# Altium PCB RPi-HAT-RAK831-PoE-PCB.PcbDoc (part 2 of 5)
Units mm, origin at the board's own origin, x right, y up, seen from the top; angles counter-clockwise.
Board outline 65 x 56 mm, 2 copper layers (Top Layer, Bottom Layer); 9 components, 14 nets, 9110 pads, 249 vias.
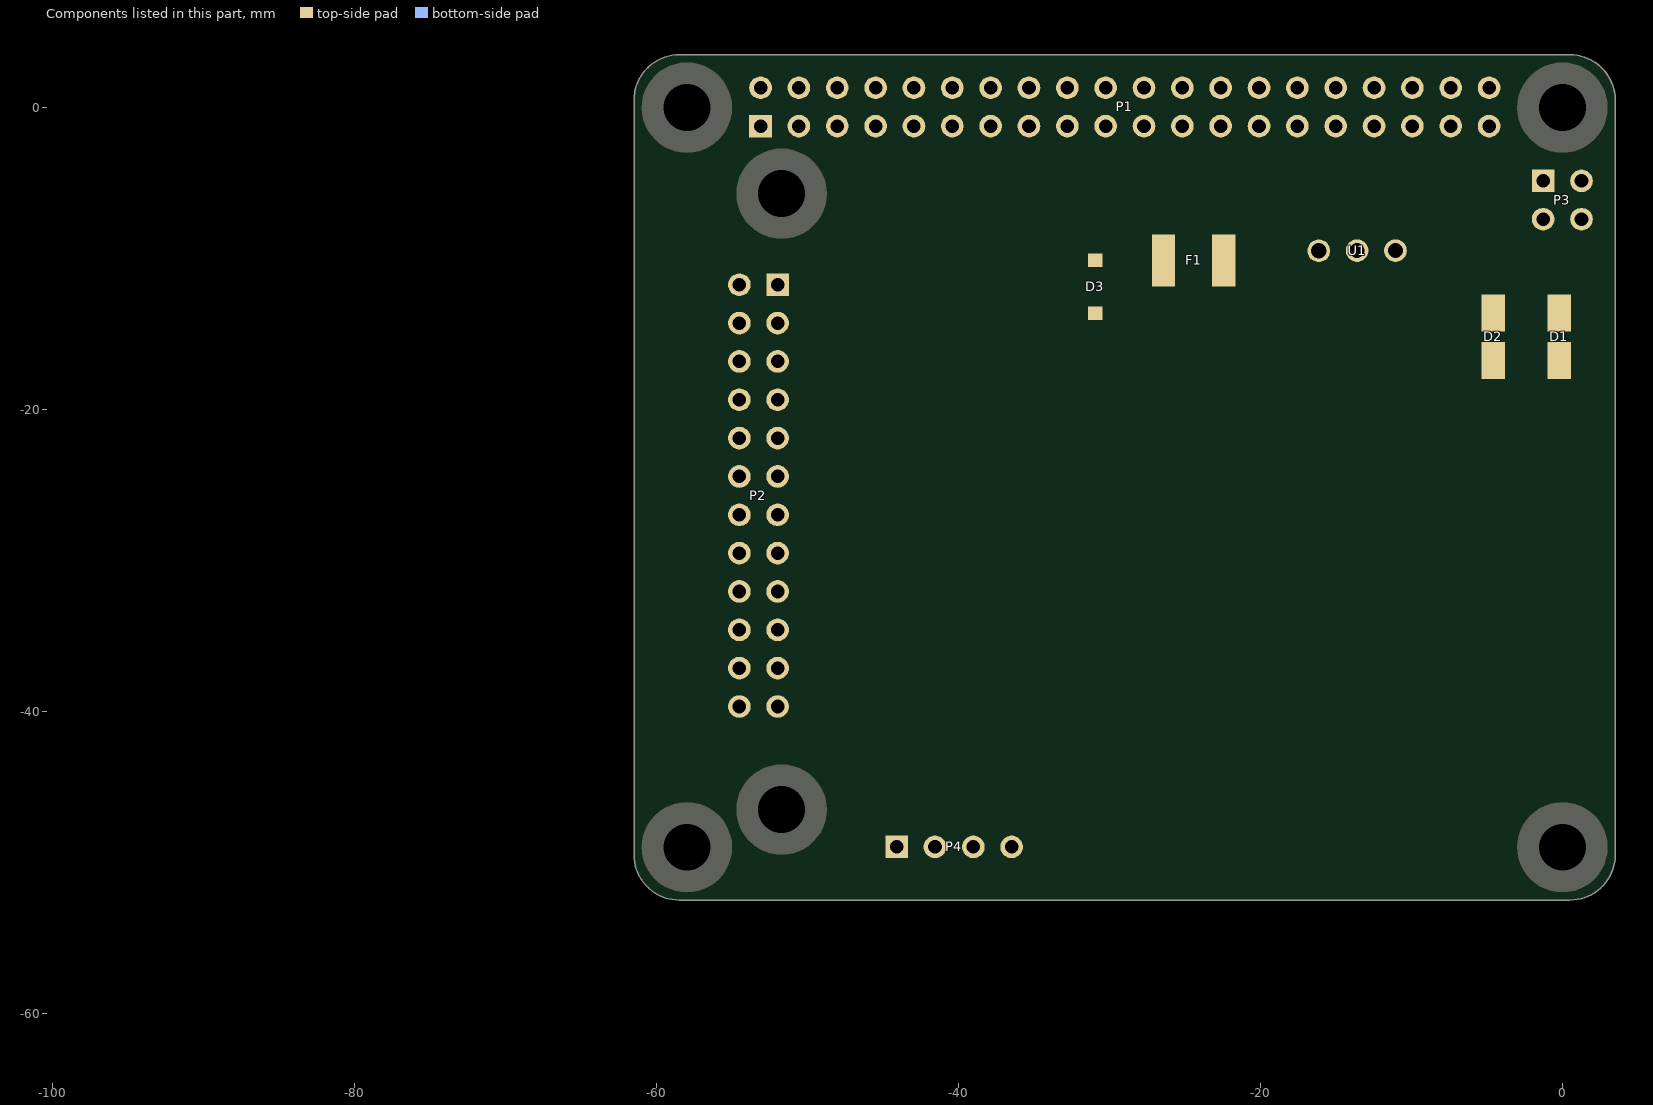
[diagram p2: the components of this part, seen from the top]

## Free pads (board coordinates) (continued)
  round 0.025 on Bottom Overlay: 1(-36.025,-43.237) 1(-36.025,-43.212) 1(-36.025,-43.186) 1(-36,-43.288) 1(-36,-43.263) 1(-35.975,-43.364) 1(-35.975,-43.339) 1(-35.975,-43.313) 1(-35.949,-43.415) 1(-35.949,-43.39) 1(-35.924,-43.491) 1(-35.924,-43.466) 1(-35.924,-43.44) 1(-35.898,-43.567) 1(-35.898,-43.542) 1(-35.898,-43.517) 1(-35.873,-43.618) 1(-35.873,-43.593) 1(-35.848,-43.694) 1(-35.848,-43.669) 1(-35.848,-43.644) 1(-35.822,-43.745) 1(-35.822,-43.72) 1(-35.797,-43.821) 1(-35.797,-43.796) 1(-35.797,-43.771) 1(-35.771,-43.898) 1(-35.771,-43.872) 1(-35.771,-43.847) 1(-35.746,-43.948) 1(-35.746,-43.923) 1(-35.721,-44.025) 1(-35.721,-43.999) 1(-35.721,-43.974) 1(-35.695,-44.101) 1(-35.695,-44.075) 1(-35.695,-44.05) 1(-35.67,-44.152) 1(-35.67,-44.126) 1(-35.644,-44.228) 1(-35.644,-44.202) 1(-35.644,-44.177) 1(-35.619,-44.279) 1(-35.619,-44.253) 1(-35.594,-44.355) 1(-35.594,-44.329) 1(-35.594,-44.304) 1(-35.568,-44.431) 1(-35.568,-44.406) 1(-35.568,-44.38) 1(-35.543,-44.482) 1(-35.543,-44.456) 1(-35.517,-44.558) 1(-35.517,-44.533) 1(-35.517,-44.507) 1(-35.492,-44.609) 1(-35.492,-44.583) 1(-35.467,-44.685) 1(-35.467,-44.66) 1(-35.467,-44.634) 1(-35.441,-44.761) 1(-35.441,-44.736) 1(-35.441,-44.71) 1(-35.416,-44.812) 1(-35.416,-44.787) 1(-35.39,-44.888) 1(-35.39,-44.863) 1(-35.39,-44.837) 1(-35.365,-44.939) 1(-35.365,-44.914) 1(-35.34,-45.015) 1(-35.34,-44.99) 1(-35.34,-44.964) 1(-35.314,-45.091) 1(-35.314,-45.066) 1(-35.314,-45.041) 1(-35.289,-45.142) 1(-35.289,-45.117) 1(-35.263,-45.218) 1(-35.263,-45.193) 1(-35.263,-45.168) 1(-35.238,-45.269) 1(-35.238,-45.244) 1(-35.213,-45.345) 1(-35.213,-45.32) 1(-35.213,-45.295) 1(-35.213,-43.186) 1(-35.187,-45.422) 1(-35.187,-45.396) 1(-35.187,-45.371) 1(-35.187,-43.263) 1(-35.187,-43.237) 1(-35.187,-43.212) 1(-35.162,-45.472) 1(-35.162,-45.447) 1(-35.162,-43.339) 1(-35.162,-43.313) 1(-35.162,-43.288) 1(-35.136,-45.549) 1(-35.136,-45.523) 1(-35.136,-45.498) 1(-35.136,-43.415) 1(-35.136,-43.39) 1(-35.136,-43.364) 1(-35.111,-45.599) 1(-35.111,-45.574) 1(-35.111,-43.491) 1(-35.111,-43.466) 1(-35.111,-43.44) 1(-35.086,-45.676) 1(-35.086,-45.65) 1(-35.086,-45.625) 1(-35.086,-43.567) 1(-35.086,-43.542) 1(-35.086,-43.517) 1(-35.06,-45.752) 1(-35.06,-45.726) 1(-35.06,-45.701) 1(-35.06,-43.644) 1(-35.06,-43.618) 1(-35.06,-43.593) 1(-35.035,-45.803) 1(-35.035,-45.777) 1(-35.035,-43.72) 1(-35.035,-43.694) 1(-35.035,-43.669) 1(-35.009,-45.879) 1(-35.009,-45.853) 1(-35.009,-45.828) 1(-35.009,-43.796) 1(-35.009,-43.771) 1(-35.009,-43.745) 1(-34.984,-45.955) 1(-34.984,-45.93) 1(-34.984,-45.904) 1(-34.984,-43.898) 1(-34.984,-43.872) 1(-34.984,-43.847) 1(-34.984,-43.821) 1(-34.959,-46.006) 1(-34.959,-45.98) 1(-34.959,-43.974) 1(-34.959,-43.948) 1(-34.959,-43.923) 1(-34.933,-46.082) 1(-34.933,-46.057) 1(-34.933,-46.031) 1(-34.933,-44.05) 1(-34.933,-44.025) 1(-34.933,-43.999) 1(-34.908,-46.133) 1(-34.908,-46.107) 1(-34.908,-44.126) 1(-34.908,-44.101) 1(-34.908,-44.075) 1(-34.882,-46.209) 1(-34.882,-46.184) 1(-34.882,-46.158) 1(-34.882,-44.202) 1(-34.882,-44.177) 1(-34.882,-44.152) 1(-34.857,-46.26) 1(-34.857,-46.234) 1(-34.857,-44.279) 1(-34.857,-44.253) 1(-34.857,-44.228) 1(-34.832,-46.311) 1(-34.832,-46.285) 1(-34.832,-44.355) 1(-34.832,-44.329) 1(-34.832,-44.304) 1(-34.806,-46.387) 1(-34.806,-46.361) 1(-34.806,-46.336) 1(-34.806,-44.431) 1(-34.806,-44.406) 1(-34.806,-44.38) 1(-34.781,-46.438) 1(-34.781,-46.412) 1(-34.781,-44.507) 1(-34.781,-44.482) 1(-34.781,-44.456) 1(-34.755,-46.463) 1(-34.755,-44.583) 1(-34.755,-44.558) 1(-34.755,-44.533) 1(-34.73,-46.514) 1(-34.73,-46.488) 1(-34.73,-44.66) 1(-34.73,-44.634) 1(-34.73,-44.609) 1(-34.705,-46.565) 1(-34.705,-46.539) 1(-34.705,-44.736) 1(-34.705,-44.71) 1(-34.705,-44.685) 1(-34.679,-46.615) 1(-34.679,-46.59) 1(-34.679,-44.812) 1(-34.679,-44.787) 1(-34.679,-44.761) 1(-34.654,-46.641) 1(-34.654,-44.914) 1(-34.654,-44.888) 1(-34.654,-44.863) 1(-34.654,-44.837) 1(-34.628,-46.666) 1(-34.628,-44.99) 1(-34.628,-44.964) 1(-34.628,-44.939) 1(-34.603,-46.717) 1(-34.603,-46.692) 1(-34.603,-45.091) 1(-34.603,-45.066) 1(-34.603,-45.041) 1(-34.603,-45.015) 1(-34.578,-46.742) 1(-34.578,-45.091) 1(-34.552,-46.768) 1(-34.552,-45.066) 1(-34.552,-45.041) 1(-34.552,-45.015) 1(-34.552,-44.99) 1(-34.552,-44.964) 1(-34.527,-46.793) 1(-34.527,-44.939) 1(-34.527,-44.914) 1(-34.527,-44.888) 1(-34.501,-46.844) 1(-34.501,-46.819) 1(-34.501,-44.863) 1(-34.501,-44.837) 1(-34.501,-44.812) 1(-34.476,-46.869) 1(-34.476,-44.787) 1(-34.476,-44.761) 1(-34.476,-44.736) 1(-34.451,-46.895) 1(-34.451,-44.71) 1(-34.451,-44.685) 1(-34.451,-44.66) 1(-34.451,-44.634) 1(-34.425,-46.92) 1(-34.425,-44.609) 1(-34.425,-44.583) 1(-34.425,-44.558) 1(-34.4,-44.533) 1(-34.4,-44.507) 1(-34.4,-44.482) 1(-34.374,-46.946) 1(-34.374,-44.456) 1(-34.374,-44.431) 1(-34.374,-44.406) 1(-34.349,-46.971) 1(-34.349,-44.38) 1(-34.349,-44.355) 1(-34.349,-44.329) 1(-34.324,-46.996) 1(-34.324,-44.304) 1(-34.324,-44.279) 1(-34.324,-44.253) 1(-34.324,-44.228) 1(-34.298,-44.202) 1(-34.298,-44.177) 1(-34.298,-44.152) 1(-34.273,-47.022) 1(-34.273,-44.126) 1(-34.273,-44.101) 1(-34.273,-44.075) 1(-34.247,-47.047) 1(-34.247,-44.05) 1(-34.247,-44.025) 1(-34.247,-43.999) 1(-34.222,-43.974) 1(-34.222,-43.948) 1(-34.222,-43.923) 1(-34.197,-47.073) 1(-34.197,-43.898) 1(-34.197,-43.872) 1(-34.197,-43.847) 1(-34.171,-45.904) 1(-34.171,-43.821) 1(-34.171,-43.796) 1(-34.171,-43.771) 1(-34.171,-43.745) 1(-34.146,-47.098) 1(-34.146,-45.955) 1(-34.146,-45.93) 1(-34.146,-45.879) 1(-34.146,-45.853) 1(-34.146,-43.72) 1(-34.146,-43.694) 1(-34.146,-43.669) 1(-34.12,-46.031) 1(-34.12,-46.006) 1(-34.12,-45.98) 1(-34.12,-45.828) 1(-34.12,-45.803) 1(-34.12,-45.777) 1(-34.12,-43.644) 1(-34.12,-43.618) 1(-34.12,-43.593) 1(-34.095,-46.082) 1(-34.095,-46.057) 1(-34.095,-45.752) 1(-34.095,-45.726) 1(-34.095,-43.567) 1(-34.095,-43.542) 1(-34.095,-43.517) 1(-34.07,-47.123) 1(-34.07,-46.133) 1(-34.07,-46.107) 1(-34.07,-45.701) 1(-34.07,-45.676) 1(-34.07,-45.65) 1(-34.07,-43.491) 1(-34.07,-43.466) 1(-34.07,-43.44) 1(-34.044,-46.209) 1(-34.044,-46.184) 1(-34.044,-46.158) 1(-34.044,-45.625) 1(-34.044,-45.599) 1(-34.044,-43.415) 1(-34.044,-43.39) 1(-34.044,-43.364) 1(-34.044,-43.339) 1(-34.019,-46.26) 1(-34.019,-46.234) 1(-34.019,-45.574) 1(-34.019,-45.549) 1(-34.019,-45.523) 1(-34.019,-43.313) 1(-34.019,-43.288) 1(-34.019,-43.263) 1(-33.993,-47.149) 1(-33.993,-46.311) 1(-33.993,-46.285) 1(-33.993,-45.498) 1(-33.993,-45.472) 1(-33.993,-43.237) 1(-33.993,-43.212) 1(-33.993,-43.186) 1(-33.968,-46.361) 1(-33.968,-46.336) 1(-33.968,-45.447) 1(-33.968,-45.422) 1(-33.968,-45.396) 1(-33.943,-46.387) 1(-33.943,-45.371) 1(-33.943,-45.345) 1(-33.917,-46.412) 1(-33.917,-45.32) 1(-33.917,-45.295) 1(-33.917,-45.269) 1(-33.892,-47.174) 1(-33.892,-46.438) 1(-33.892,-45.244) 1(-33.892,-45.218) 1(-33.866,-46.463) 1(-33.866,-45.193) 1(-33.866,-45.168) 1(-33.866,-45.142) 1(-33.841,-46.488) 1(-33.841,-45.117) 1(-33.841,-45.091) 1(-33.816,-46.514) 1(-33.816,-45.066) 1(-33.816,-45.041) 1(-33.816,-45.015) 1(-33.79,-44.99) 1(-33.79,-44.964) 1(-33.765,-46.539) 1(-33.765,-44.939) 1(-33.765,-44.914) 1(-33.739,-44.888) 1(-33.739,-44.863) 1(-33.739,-44.837) 1(-33.714,-44.812) 1(-33.714,-44.787) 1(-33.689,-44.761) 1(-33.689,-44.736) 1(-33.689,-44.71) 1(-33.663,-46.565) 1(-33.663,-44.685) 1(-33.663,-44.66) 1(-33.638,-44.634) 1(-33.638,-44.609) 1(-33.638,-44.583) 1(-33.612,-44.558) 1(-33.612,-44.533) 1(-33.587,-44.507) 1(-33.587,-44.482) 1(-33.587,-44.456) 1(-33.562,-44.431) 1(-33.562,-44.406) 1(-33.536,-44.38) 1(-33.536,-44.355) 1(-33.536,-44.329) 1(-33.511,-44.304) 1(-33.511,-44.279) 1(-33.485,-44.253) 1(-33.485,-44.228) 1(-33.485,-44.202) 1(-33.46,-46.565) 1(-33.46,-44.177) 1(-33.46,-44.152) 1(-33.435,-47.174) 1(-33.435,-44.126) 1(-33.435,-44.101) 1(-33.409,-44.075) 1(-33.409,-44.05) 1(-33.409,-44.025) 1(-33.384,-43.999) 1(-33.384,-43.974) 1(-33.358,-46.539) 1(-33.358,-43.948) 1(-33.358,-43.923) 1(-33.358,-43.898) 1(-33.333,-43.872) 1(-33.333,-43.847) 1(-33.308,-46.514) 1(-33.308,-43.821) 1(-33.308,-43.796) 1(-33.308,-43.771) 1(-33.282,-47.149) 1(-33.282,-43.745) 1(-33.282,-43.72) 1(-33.257,-46.488) 1(-33.257,-43.694) 1(-33.257,-43.669) 1(-33.257,-43.644) 1(-33.231,-43.618) 1(-33.231,-43.593) 1(-33.206,-47.123) 1(-33.206,-47.098) 1(-33.206,-47.073) 1(-33.206,-47.047) 1(-33.206,-47.022) 1(-33.206,-46.996) 1(-33.206,-46.971) 1(-33.206,-46.946) 1(-33.206,-46.92) 1(-33.206,-46.895) 1(-33.206,-46.869) 1(-33.206,-46.844) 1(-33.206,-46.819) 1(-33.206,-46.793) 1(-33.206,-46.768) 1(-33.206,-46.742) 1(-33.206,-46.717) 1(-33.206,-46.692) 1(-33.206,-46.666) 1(-33.206,-46.641) 1(-33.206,-46.615) 1(-33.206,-46.59) 1(-33.206,-46.565) 1(-33.206,-46.539) 1(-33.206,-46.514) 1(-33.206,-46.488) 1(-33.206,-43.567) 1(-33.206,-43.542) 1(-33.206,-43.517) 1(-33.181,-43.491) 1(-33.181,-43.466) 1(-33.155,-43.44) 1(-33.155,-43.415) 1(-33.155,-43.39) 1(-33.13,-43.364) 1(-33.13,-43.339) 1(-33.104,-43.313) 1(-33.104,-43.288) 1(-33.079,-43.263) 1(-33.079,-43.237) 1(-33.079,-43.212) 1(-33.054,-43.186) 1(-32.774,-45.904) 1(-32.774,-45.879) 1(-32.774,-45.853) 1(-32.774,-45.828) 1(-32.774,-45.803) 1(-32.774,-45.777) 1(-32.774,-45.752) 1(-32.774,-45.726) 1(-32.774,-45.701) 1(-32.774,-45.676) 1(-32.774,-45.65) 1(-32.774,-45.625) 1(-32.774,-45.599) 1(-32.774,-45.574) 1(-32.774,-45.549) 1(-32.774,-45.523) 1(-32.774,-45.498) 1(-32.774,-45.472) 1(-32.774,-45.447) 1(-32.774,-45.422) 1(-32.774,-45.396) 1(-32.774,-45.371) 1(-32.774,-45.345) 1(-32.774,-45.32) 1(-32.774,-45.295) 1(-32.774,-45.269) 1(-32.774,-45.244) 1(-32.774,-45.218) 1(-32.774,-45.193) 1(-32.774,-45.168) 1(-32.774,-45.142) 1(-32.774,-45.117) 1(-32.774,-45.091) 1(-32.774,-45.066) 1(-32.774,-45.041) 1(-32.774,-45.015) 1(-32.774,-44.99) 1(-32.774,-44.964) 1(-32.774,-44.939) 1(-32.774,-44.914) 1(-32.774,-44.888) 1(-32.774,-44.863) 1(-32.774,-44.837) 1(-32.774,-44.812) 1(-32.774,-44.787) 1(-32.774,-44.761) 1(-32.774,-44.736) 1(-32.774,-44.71) 1(-32.774,-44.685) 1(-32.774,-44.66) 1(-32.774,-44.634) 1(-32.774,-44.609) 1(-32.774,-44.583) 1(-32.774,-44.558) 1(-32.774,-44.533) 1(-32.774,-44.507) 1(-32.774,-44.482) 1(-32.774,-44.456) 1(-32.774,-44.431) 1(-32.774,-44.406) 1(-32.774,-44.38) 1(-32.774,-44.355) 1(-32.774,-44.329) 1(-32.774,-44.304) 1(-32.774,-44.279) 1(-32.774,-44.253) 1(-32.774,-44.228) 1(-32.774,-44.202) 1(-32.774,-44.177) 1(-32.774,-44.152) 1(-32.774,-44.126) 1(-32.774,-44.101) 1(-32.774,-44.075) 1(-32.749,-44.05) 1(-32.749,-44.025) 1(-32.749,-43.999) 1(-32.749,-43.974) 1(-32.749,-43.948) 1(-32.749,-43.923) 1(-32.723,-43.898) 1(-32.723,-43.872) 1(-32.723,-43.847) 1(-32.723,-43.821) 1(-32.698,-43.796) 1(-32.698,-43.771) 1(-32.698,-43.745) 1(-32.673,-43.72) 1(-32.673,-43.694) 1(-32.673,-43.669) 1(-32.647,-43.644) 1(-32.647,-43.618) 1(-32.622,-43.593) 1(-32.596,-43.567) 1(-32.596,-43.542) 1(-32.571,-43.517) 1(-32.546,-43.491) 1(-32.546,-43.466) 1(-32.52,-43.44) 1(-32.495,-43.415) 1(-32.469,-43.39) 1(-32.444,-43.364) 1(-32.393,-43.339) 1(-32.368,-43.313) 1(-32.317,-43.288) 1(-32.292,-43.263) 1(-32.241,-43.237) 1(-32.165,-43.212) 1(-32.088,-43.186) 1(-31.987,-44.863) 1(-31.987,-44.837) 1(-31.987,-44.812) 1(-31.987,-44.787) 1(-31.987,-44.761) 1(-31.987,-44.736) 1(-31.987,-44.71) 1(-31.987,-44.685) 1(-31.987,-44.66) 1(-31.987,-44.634) 1(-31.987,-44.126) 1(-31.987,-44.101) 1(-31.987,-44.075) 1(-31.987,-43.161) 1(-31.961,-45.904) 1(-31.961,-45.879) 1(-31.961,-45.853) 1(-31.961,-45.828) 1(-31.961,-45.803) 1(-31.961,-45.777) 1(-31.961,-45.752) 1(-31.961,-45.726) 1(-31.961,-45.701) 1(-31.961,-45.676) 1(-31.961,-45.65) 1(-31.961,-45.625) 1(-31.961,-45.599) 1(-31.961,-45.015) 1(-31.961,-44.99) 1(-31.961,-44.964) 1(-31.961,-44.939) 1(-31.961,-44.914) 1(-31.961,-44.888) 1(-31.961,-44.05) 1(-31.961,-44.025) 1(-31.961,-43.999) 1(-31.961,-43.974) 1(-31.961,-43.948) 1(-31.936,-45.599) 1(-31.936,-45.066) 1(-31.936,-45.041) 1(-31.936,-43.923) 1(-31.936,-43.898) 1(-31.911,-45.65) 1(-31.911,-45.625) 1(-31.911,-45.142) 1(-31.911,-45.117) 1(-31.911,-45.091) 1(-31.911,-43.872) 1(-31.911,-43.847) 1(-31.885,-45.676) 1(-31.885,-45.168) 1(-31.885,-44.152) 1(-31.885,-43.821) 1(-31.86,-45.701) 1(-31.86,-45.218) 1(-31.86,-45.193) 1(-31.86,-43.796) 1(-31.834,-45.726) 1(-31.834,-45.244) 1(-31.834,-43.771) 1(-31.834,-43.136) 1(-31.809,-45.752) 1(-31.809,-45.269) 1(-31.809,-43.745) 1(-31.784,-45.295) 1(-31.784,-44.634) 1(-31.784,-43.72) 1(-31.758,-45.777) 1(-31.758,-45.32) 1(-31.733,-45.803) 1(-31.707,-45.828) 1(-31.707,-45.345) 1(-31.707,-43.694) 1(-31.682,-45.371) 1(-31.682,-44.177) 1(-31.657,-45.853) 1(-31.631,-45.396) 1(-31.631,-43.669) 1(-31.606,-45.879) 1(-31.606,-44.66) 1(-31.555,-45.904) 1(-31.53,-45.422) 1(-31.504,-44.202) 1(-31.479,-45.93) 1(-31.428,-44.685) 1(-31.352,-45.955) 1(-31.352,-43.136) 1(-31.326,-45.422) 1(-31.326,-44.71) 1(-31.326,-44.228) 1(-31.326,-43.669) 1(-31.276,-44.736) 1(-31.25,-45.396) 1(-31.225,-44.761) 1(-31.199,-45.371) 1(-31.174,-45.345) 1(-31.174,-44.787) 1(-31.174,-43.694) 1(-31.174,-43.161) 1(-31.149,-45.32) 1(-31.149,-44.812) 1(-31.149,-44.253) 1(-31.123,-45.295) 1(-31.123,-44.863) 1(-31.123,-44.837) 1(-31.098,-45.269) 1(-31.098,-45.244) 1(-31.098,-44.914) 1(-31.098,-44.888) 1(-31.072,-45.218) 1(-31.072,-45.193) 1(-31.072,-45.168) 1(-31.072,-45.142) 1(-31.072,-45.015) 1(-31.072,-44.99) 1(-31.072,-44.964) 1(-31.072,-44.939) 1(-31.072,-43.72) 1(-31.047,-45.117) 1(-31.047,-45.091) 1(-31.047,-45.066) 1(-31.047,-45.041) 1(-31.047,-43.186) 1(-31.022,-44.279) 1(-30.996,-43.745) 1(-30.971,-45.955) 1(-30.945,-43.212) 1(-30.92,-44.304) 1(-30.92,-43.771) 1(-30.869,-43.796) 1(-30.844,-45.93) 1(-30.844,-44.329) 1(-30.844,-43.237) 1(-30.818,-43.821) 1(-30.793,-44.355) 1(-30.768,-45.904) 1(-30.768,-43.847) 1(-30.768,-43.263) 1(-30.742,-44.38) 1(-30.717,-43.872) 1(-30.691,-45.879) 1(-30.691,-44.406) 1(-30.691,-43.898) 1(-30.691,-43.288) 1(-30.666,-45.853) 1(-30.641,-44.431) 1(-30.641,-43.923) 1(-30.615,-45.828) 1(-30.615,-44.456) 1(-30.615,-43.948) 1(-30.615,-43.313) 1(-30.59,-45.803) 1(-30.564,-44.482) 1(-30.564,-43.339) 1(-30.539,-45.777) 1(-30.539,-44.507) 1(-30.539,-43.948) 1(-30.539,-43.923) 1(-30.539,-43.898) 1(-30.539,-43.872) 1(-30.539,-43.847) 1(-30.539,-43.821) 1(-30.539,-43.796) 1(-30.539,-43.771) 1(-30.539,-43.745) 1(-30.539,-43.72) 1(-30.539,-43.694) 1(-30.539,-43.669) 1(-30.539,-43.644) 1(-30.539,-43.618) 1(-30.539,-43.593) 1(-30.539,-43.567) 1(-30.539,-43.542) 1(-30.539,-43.517) 1(-30.539,-43.491) 1(-30.539,-43.466) 1(-30.539,-43.44) 1(-30.539,-43.415) 1(-30.539,-43.39) 1(-30.539,-43.364) 1(-30.514,-45.752) 1(-30.514,-44.533) 1(-30.488,-45.726) 1(-30.488,-44.558) 1(-30.463,-45.701) 1(-30.463,-44.583) 1(-30.437,-45.676) 1(-30.437,-45.65) 1(-30.437,-44.634) 1(-30.437,-44.609) 1(-30.412,-45.625) 1(-30.412,-44.66) 1(-30.387,-45.599) 1(-30.387,-45.574) 1(-30.387,-44.71) 1(-30.387,-44.685) 1(-30.361,-45.549) 1(-30.361,-45.523) 1(-30.361,-44.761) 1(-30.361,-44.736) 1(-30.336,-45.498) 1(-30.336,-45.472) 1(-30.336,-44.837) 1(-30.336,-44.812) 1(-30.336,-44.787) 1(-30.31,-45.447) 1(-30.31,-45.422) 1(-30.31,-45.396) 1(-30.31,-45.371) 1(-30.31,-44.914) 1(-30.31,-44.888) 1(-30.31,-44.863) 1(-30.285,-45.345) 1(-30.285,-45.32) 1(-30.285,-45.295) 1(-30.285,-45.269) 1(-30.285,-45.244) 1(-30.285,-45.218) 1(-30.285,-45.193) 1(-30.285,-45.168) 1(-30.285,-45.142) 1(-30.285,-45.117) 1(-30.285,-45.091) 1(-30.285,-45.066) 1(-30.285,-45.041) 1(-30.285,-45.015) 1(-30.285,-44.99) 1(-30.285,-44.964) 1(-30.285,-44.939) 1(-30.107,-43.212) 1(-30.107,-43.186) 1(-30.082,-43.313) 1(-30.082,-43.288) 1(-30.082,-43.263) 1(-30.082,-43.237) 1(-30.056,-43.39) 1(-30.056,-43.364) 1(-30.056,-43.339) 1(-30.031,-43.491) 1(-30.031,-43.466) 1(-30.031,-43.44) 1(-30.031,-43.415) 1(-30.006,-43.567) 1(-30.006,-43.542) 1(-30.006,-43.517) 1(-29.98,-43.669) 1(-29.98,-43.644) 1(-29.98,-43.618) 1(-29.98,-43.593) 1(-29.955,-43.745) 1(-29.955,-43.72) 1(-29.955,-43.694) 1(-29.929,-43.821) 1(-29.929,-43.796) 1(-29.929,-43.771) 1(-29.904,-43.923) 1(-29.904,-43.898) 1(-29.904,-43.872) 1(-29.904,-43.847) 1(-29.879,-43.999) 1(-29.879,-43.974) 1(-29.879,-43.948) 1(-29.853,-44.101) 1(-29.853,-44.075) 1(-29.853,-44.05) 1(-29.853,-44.025) 1(-29.828,-44.177) 1(-29.828,-44.152) 1(-29.828,-44.126) 1(-29.802,-44.279) 1(-29.802,-44.253) 1(-29.802,-44.228) 1(-29.802,-44.202) 1(-29.777,-44.355) 1(-29.777,-44.329) 1(-29.777,-44.304) 1(-29.752,-44.456) 1(-29.752,-44.431) 1(-29.752,-44.406) 1(-29.752,-44.38) 1(-29.726,-44.533) 1(-29.726,-44.507) 1(-29.726,-44.482) 1(-29.701,-44.634) 1(-29.701,-44.609) 1(-29.701,-44.583) 1(-29.701,-44.558) 1(-29.675,-44.71) 1(-29.675,-44.685) 1(-29.675,-44.66) 1(-29.65,-44.812) 1(-29.65,-44.787) 1(-29.65,-44.761) 1(-29.65,-44.736) 1(-29.625,-44.888) 1(-29.625,-44.863) 1(-29.625,-44.837) 1(-29.599,-44.964) 1(-29.599,-44.939) 1(-29.599,-44.914) 1(-29.574,-45.066) 1(-29.574,-45.041) 1(-29.574,-45.015) 1(-29.574,-44.99) 1(-29.548,-45.142) 1(-29.548,-45.117) 1(-29.548,-45.091) 1(-29.523,-45.244) 1(-29.523,-45.218) 1(-29.523,-45.193) 1(-29.523,-45.168) 1(-29.498,-45.32) 1(-29.498,-45.295) 1(-29.498,-45.269) 1(-29.472,-45.422) 1(-29.472,-45.396) 1(-29.472,-45.371) 1(-29.472,-45.345) 1(-29.447,-45.498) 1(-29.447,-45.472) 1(-29.447,-45.447) 1(-29.421,-45.599) 1(-29.421,-45.574) 1(-29.421,-45.549) 1(-29.421,-45.523) 1(-29.396,-45.676) 1(-29.396,-45.65) 1(-29.396,-45.625) 1(-29.371,-45.777) 1(-29.371,-45.752) 1(-29.371,-45.726) 1(-29.371,-45.701) 1(-29.345,-45.853) 1(-29.345,-45.828) 1(-29.345,-45.803) 1(-29.32,-45.904) 1(-29.32,-45.879) 1(-29.32,-43.263) 1(-29.32,-43.237) 1(-29.32,-43.212) 1(-29.32,-43.186) 1(-29.294,-43.39) 1(-29.294,-43.364) 1(-29.294,-43.339) 1(-29.294,-43.313) 1(-29.294,-43.288) 1(-29.269,-43.517) 1(-29.269,-43.491) 1(-29.269,-43.466) 1(-29.269,-43.44) 1(-29.269,-43.415) 1(-29.244,-43.618) 1(-29.244,-43.593) 1(-29.244,-43.567) 1(-29.244,-43.542) 1(-29.218,-43.745) 1(-29.218,-43.72) 1(-29.218,-43.694) 1(-29.218,-43.669) 1(-29.218,-43.644) 1(-29.193,-43.872) 1(-29.193,-43.847) 1(-29.193,-43.821) 1(-29.193,-43.796) 1(-29.193,-43.771) 1(-29.167,-43.999) 1(-29.167,-43.974) 1(-29.167,-43.948) 1(-29.167,-43.923) 1(-29.167,-43.898) 1(-29.142,-44.101) 1(-29.142,-44.075) 1(-29.142,-44.05) 1(-29.142,-44.025) 1(-29.117,-44.228) 1(-29.117,-44.202) 1(-29.117,-44.177) 1(-29.117,-44.152) 1(-29.117,-44.126) 1(-29.091,-44.355) 1(-29.091,-44.329) 1(-29.091,-44.304) 1(-29.091,-44.279) 1(-29.091,-44.253) 1(-29.066,-44.482) 1(-29.066,-44.456) 1(-29.066,-44.431) 1(-29.066,-44.406) 1(-29.066,-44.38) 1(-29.04,-44.583) 1(-29.04,-44.558) 1(-29.04,-44.533) 1(-29.04,-44.507) 1(-29.015,-44.71) 1(-29.015,-44.685) 1(-29.015,-44.66) 1(-29.015,-44.634) 1(-29.015,-44.609) 1(-28.99,-44.837) 1(-28.99,-44.812) 1(-28.99,-44.787) 1(-28.99,-44.761) 1(-28.99,-44.736) 1(-28.964,-44.964) 1(-28.964,-44.939) 1(-28.964,-44.914) 1(-28.964,-44.888) 1(-28.964,-44.863) 1(-28.939,-45.091) 1(-28.939,-45.066) 1(-28.939,-45.041) 1(-28.939,-45.015) 1(-28.939,-44.99) 1(-28.913,-45.091) 1(-28.888,-45.066) 1(-28.888,-45.041) 1(-28.888,-45.015) 1(-28.888,-44.99) 1(-28.888,-44.964) 1(-28.863,-44.939) 1(-28.863,-44.914) 1(-28.863,-44.888) 1(-28.863,-44.863) 1(-28.863,-44.837) 1(-28.837,-44.812) 1(-28.837,-44.787) 1(-28.837,-44.761) 1(-28.837,-44.736) 1(-28.812,-44.71) 1(-28.812,-44.685) 1(-28.812,-44.66) 1(-28.812,-44.634) 1(-28.786,-44.609) 1(-28.786,-44.583) 1(-28.786,-44.558) 1(-28.786,-44.533) 1(-28.761,-44.507) 1(-28.761,-44.482) 1(-28.761,-44.456) 1(-28.761,-44.431) 1(-28.736,-44.406) 1(-28.736,-44.38) 1(-28.736,-44.355) 1(-28.736,-44.329) 1(-28.71,-44.304) 1(-28.71,-44.279) 1(-28.71,-44.253) 1(-28.71,-44.228) 1(-28.685,-44.202) 1(-28.685,-44.177) 1(-28.685,-44.152) 1(-28.685,-44.126) 1(-28.685,-44.101) 1(-28.659,-44.075) 1(-28.659,-44.05) 1(-28.659,-44.025) 1(-28.659,-43.999) 1(-28.634,-43.974) 1(-28.634,-43.948) 1(-28.634,-43.923) 1(-28.634,-43.898) 1(-28.609,-43.872) 1(-28.609,-43.847) 1(-28.609,-43.821) 1(-28.609,-43.796) 1(-28.583,-43.771) 1(-28.583,-43.745) 1(-28.583,-43.72) 1(-28.583,-43.694) 1(-28.558,-43.669) 1(-28.558,-43.644) 1(-28.558,-43.618) 1(-28.558,-43.593) 1(-28.532,-43.567) 1(-28.532,-43.542) 1(-28.532,-43.517) 1(-28.532,-43.491) 1(-28.507,-43.466) 1(-28.507,-43.44) 1(-28.507,-43.415) 1(-28.507,-43.39) 1(-28.482,-43.364) 1(-28.482,-43.339) 1(-28.482,-43.313) 1(-28.482,-43.288) 1(-28.482,-43.263) 1(-28.456,-43.237) 1(-28.456,-43.212) 1(-28.456,-43.186) 1(-28.431,-45.904) 1(-28.431,-45.879) 1(-28.431,-45.853) 1(-28.405,-45.828) 1(-28.405,-45.803) 1(-28.405,-45.777) 1(-28.405,-45.752) 1(-28.38,-45.726) 1(-28.38,-45.701) 1(-28.38,-45.676) 1(-28.38,-45.65) 1(-28.355,-45.625) 1(-28.355,-45.599) 1(-28.355,-45.574) 1(-28.355,-45.549) 1(-28.329,-45.523) 1(-28.329,-45.498) 1(-28.329,-45.472) 1(-28.329,-45.447) 1(-28.304,-45.422) 1(-28.304,-45.396) 1(-28.304,-45.371) 1(-28.304,-45.345) 1(-28.278,-45.32) 1(-28.278,-45.295) 1(-28.278,-45.269) 1(-28.278,-45.244) 1(-28.253,-45.218) 1(-28.253,-45.193) 1(-28.253,-45.168) 1(-28.253,-45.142) 1(-28.228,-45.117) 1(-28.228,-45.091) 1(-28.228,-45.066) 1(-28.228,-45.041) 1(-28.202,-45.015) 1(-28.202,-44.99) 1(-28.202,-44.964) 1(-28.202,-44.939) 1(-28.177,-44.914) 1(-28.177,-44.888) 1(-28.177,-44.863) 1(-28.177,-44.837) 1(-28.151,-44.812) 1(-28.151,-44.787) 1(-28.151,-44.761) 1(-28.126,-44.736) 1(-28.126,-44.71) 1(-28.126,-44.685) 1(-28.126,-44.66) 1(-28.101,-44.634) 1(-28.101,-44.609) 1(-28.101,-44.583) 1(-28.101,-44.558) 1(-28.075,-44.533) 1(-28.075,-44.507) 1(-28.075,-44.482) 1(-28.075,-44.456) 1(-28.05,-44.431) 1(-28.05,-44.406) 1(-28.05,-44.38) 1(-28.05,-44.355) 1(-28.024,-44.329) 1(-28.024,-44.304) 1(-28.024,-44.279) 1(-28.024,-44.253) 1(-27.999,-44.228) 1(-27.999,-44.202) 1(-27.999,-44.177) 1(-27.999,-44.152) 1(-27.999,-44.126) 1(-27.999,-44.101) 1(-27.974,-44.152) 1(-27.974,-44.126) 1(-27.974,-44.101) 1(-27.948,-44.279) 1(-27.948,-44.253) 1(-27.948,-44.228) 1(-27.948,-44.202) 1(-27.948,-44.177) 1(-27.923,-44.355) 1(-27.923,-44.329) 1(-27.923,-44.304) 1(-27.897,-44.456) 1(-27.897,-44.431) 1(-27.897,-44.406) 1(-27.897,-44.38) 1(-27.872,-44.558) 1(-27.872,-44.533) 1(-27.872,-44.507) 1(-27.872,-44.482) 1(-27.847,-44.634) 1(-27.847,-44.609) 1(-27.847,-44.583) 1(-27.821,-44.736) 1(-27.821,-44.71) 1(-27.821,-44.685) 1(-27.821,-44.66) 1(-27.796,-44.837) 1(-27.796,-44.812) 1(-27.796,-44.787) 1(-27.796,-44.761) 1(-27.77,-44.914) 1(-27.77,-44.888) 1(-27.77,-44.863) 1(-27.745,-45.015) 1(-27.745,-44.99) 1(-27.745,-44.964) 1(-27.745,-44.939) 1(-27.72,-45.117) 1(-27.72,-45.091) 1(-27.72,-45.066) 1(-27.72,-45.041) 1(-27.694,-45.193) 1(-27.694,-45.168) 1(-27.694,-45.142) 1(-27.669,-45.295) 1(-27.669,-45.269) 1(-27.669,-45.244) 1(-27.669,-45.218) 1(-27.643,-45.396) 1(-27.643,-45.371) 1(-27.643,-45.345) 1(-27.643,-45.32) 1(-27.643,-43.237) 1(-27.643,-43.212) 1(-27.643,-43.186) 1(-27.618,-45.472) 1(-27.618,-45.447) 1(-27.618,-45.422) 1(-27.618,-43.339) 1(-27.618,-43.313) 1(-27.618,-43.288) 1(-27.618,-43.263) 1(-27.593,-45.574) 1(-27.593,-45.549) 1(-27.593,-45.523) 1(-27.593,-45.498) 1(-27.593,-43.415) 1(-27.593,-43.39) 1(-27.593,-43.364) 1(-27.567,-45.676) 1(-27.567,-45.65) 1(-27.567,-45.625) 1(-27.567,-45.599) 1(-27.567,-43.517) 1(-27.567,-43.491) 1(-27.567,-43.466) 1(-27.567,-43.44) 1(-27.542,-45.752) 1(-27.542,-45.726) 1(-27.542,-45.701) 1(-27.542,-43.618) 1(-27.542,-43.593) 1(-27.542,-43.567) 1(-27.542,-43.542) 1(-27.516,-45.853) 1(-27.516,-45.828) 1(-27.516,-45.803) 1(-27.516,-45.777) 1(-27.516,-43.694) 1(-27.516,-43.669) 1(-27.516,-43.644) 1(-27.491,-45.904) 1(-27.491,-45.879) 1(-27.491,-43.796) 1(-27.491,-43.771) 1(-27.491,-43.745) 1(-27.491,-43.72) 1(-27.466,-43.898) 1(-27.466,-43.872) 1(-27.466,-43.847) 1(-27.466,-43.821) 1(-27.44,-43.974) 1(-27.44,-43.948) 1(-27.44,-43.923) 1(-27.415,-44.075) 1(-27.415,-44.05) 1(-27.415,-44.025) 1(-27.415,-43.999) 1(-27.389,-44.177) 1(-27.389,-44.152) 1(-27.389,-44.126) 1(-27.389,-44.101) 1(-27.364,-44.253) 1(-27.364,-44.228) 1(-27.364,-44.202) 1(-27.339,-44.355) 1(-27.339,-44.329) 1(-27.339,-44.304) 1(-27.339,-44.279) 1(-27.313,-44.456) 1(-27.313,-44.431) 1(-27.313,-44.406) 1(-27.313,-44.38) 1(-27.288,-44.533) 1(-27.288,-44.507) 1(-27.288,-44.482) 1(-27.262,-44.634) 1(-27.262,-44.609) 1(-27.262,-44.583) 1(-27.262,-44.558) 1(-27.237,-44.736) 1(-27.237,-44.71) 1(-27.237,-44.685) 1(-27.237,-44.66) 1(-27.212,-44.812) 1(-27.212,-44.787) 1(-27.212,-44.761) 1(-27.186,-44.914) 1(-27.186,-44.888) 1(-27.186,-44.863) 1(-27.186,-44.837) 1(-27.161,-45.015) 1(-27.161,-44.99) 1(-27.161,-44.964) 1(-27.161,-44.939) 1(-27.135,-45.142) 1(-27.135,-45.117) 1(-27.135,-45.091) 1(-27.135,-45.066) 1(-27.135,-45.041) 1(-27.11,-45.142) 1(-27.11,-45.117) 1(-27.11,-45.091) 1(-27.11,-45.066) 1(-27.11,-45.041) 1(-27.11,-45.015) 1(-27.085,-44.99) 1(-27.085,-44.964) 1(-27.085,-44.939) 1(-27.085,-44.914) 1(-27.085,-44.888) 1(-27.059,-44.863) 1(-27.059,-44.837) 1(-27.059,-44.812) 1(-27.059,-44.787) 1(-27.034,-44.761) 1(-27.034,-44.736) 1(-27.034,-44.71) 1(-27.034,-44.685) 1(-27.034,-44.66) 1(-27.008,-44.634) 1(-27.008,-44.609) 1(-27.008,-44.583) 1(-27.008,-44.558) 1(-26.983,-44.533) 1(-26.983,-44.507) 1(-26.983,-44.482) 1(-26.983,-44.456) 1(-26.958,-44.431) 1(-26.958,-44.406) 1(-26.958,-44.38) 1(-26.958,-44.355) 1(-26.958,-44.329) 1(-26.932,-44.304) 1(-26.932,-44.279) 1(-26.932,-44.253) 1(-26.932,-44.228) 1(-26.907,-44.202) 1(-26.907,-44.177) 1(-26.907,-44.152) 1(-26.907,-44.126) 1(-26.907,-44.101) 1(-26.881,-44.075) 1(-26.881,-44.05) 1(-26.881,-44.025) 1(-26.881,-43.999) 1(-26.856,-43.974) 1(-26.856,-43.948) 1(-26.856,-43.923) 1(-26.856,-43.898) 1(-26.856,-43.872) 1(-26.831,-43.847) 1(-26.831,-43.821) 1(-26.831,-43.796) 1(-26.831,-43.771) 1(-26.805,-43.745) 1(-26.805,-43.72) 1(-26.805,-43.694) 1(-26.805,-43.669) 1(-26.805,-43.644) 1(-26.78,-43.618) 1(-26.78,-43.593) 1(-26.78,-43.567) 1(-26.78,-43.542) 1(-26.754,-43.517) 1(-26.754,-43.491) 1(-26.754,-43.466) 1(-26.754,-43.44) 1(-26.754,-43.415) 1(-26.729,-43.39) 1(-26.729,-43.364) 1(-26.729,-43.339) 1(-26.729,-43.313) 1(-26.704,-43.288) 1(-26.704,-43.263) 1(-26.704,-43.237) 1(-26.704,-43.212) 1(-26.704,-43.186) 1(-26.627,-45.904) 1(-26.602,-45.879) 1(-26.602,-45.853) 1(-26.602,-45.828) 1(-26.577,-45.803) 1(-26.577,-45.777) 1(-26.577,-45.752) 1(-26.577,-45.726) 1(-26.551,-45.701) 1(-26.551,-45.676) 1(-26.551,-45.65) 1(-26.526,-45.625) 1(-26.526,-45.599) 1(-26.526,-45.574) 1(-26.526,-45.549) 1(-26.5,-45.523) 1(-26.5,-45.498) 1(-26.5,-45.472) 1(-26.475,-45.447) 1(-26.475,-45.422) 1(-26.475,-45.396) 1(-26.475,-45.371) 1(-26.45,-45.345) 1(-26.45,-45.32) 1(-26.45,-45.295) 1(-26.424,-45.269) 1(-26.424,-45.244) 1(-26.424,-45.218) 1(-26.399,-45.193) 1(-26.399,-45.168) 1(-26.399,-45.142) 1(-26.399,-45.117) 1(-26.373,-45.091) 1(-26.373,-45.066) 1(-26.373,-45.041) 1(-26.348,-45.015) 1(-26.348,-44.99) 1(-26.348,-44.964) 1(-26.348,-44.939) 1(-26.323,-44.914) 1(-26.323,-44.888) 1(-26.323,-44.863) 1(-26.297,-44.837) 1(-26.297,-44.812) 1(-26.297,-44.787) 1(-26.297,-44.761) 1(-26.272,-44.736) 1(-26.272,-44.71) 1(-26.272,-44.685) 1(-26.246,-44.66) 1(-26.246,-44.634) 1(-26.246,-44.609) 1(-26.246,-44.583) 1(-26.221,-44.558) 1(-26.221,-44.533) 1(-26.221,-44.507) 1(-26.196,-44.482) 1(-26.196,-44.456) 1(-26.196,-44.431) 1(-26.196,-44.406) 1(-26.17,-44.38) 1(-26.17,-44.355) 1(-26.17,-44.329) 1(-26.145,-44.304) 1(-26.145,-44.279) 1(-26.145,-44.253) 1(-26.145,-44.228) 1(-26.119,-44.202) 1(-26.119,-44.177) 1(-26.119,-44.152) 1(-26.094,-44.126) 1(-26.094,-44.101) 1(-26.094,-44.075) 1(-26.094,-44.05) 1(-26.069,-44.025) 1(-26.069,-43.999) 1(-26.069,-43.974) 1(-26.043,-43.948) 1(-26.043,-43.923) 1(-26.043,-43.898) 1(-26.043,-43.872) 1(-26.018,-43.847) 1(-26.018,-43.821) 1(-26.018,-43.796) 1(-25.992,-43.771) 1(-25.992,-43.745) 1(-25.992,-43.72) 1(-25.992,-43.694) 1(-25.967,-43.669) 1(-25.967,-43.644) 1(-25.967,-43.618) 1(-25.942,-43.593) 1(-25.942,-43.567) 1(-25.942,-43.542) 1(-25.942,-43.517) 1(-25.916,-43.491) 1(-25.916,-43.466) 1(-25.916,-43.44) 1(-25.891,-43.415) 1(-25.891,-43.39) 1(-25.891,-43.364) 1(-25.891,-43.339) 1(-25.865,-43.313) 1(-25.865,-43.288) 1(-25.865,-43.263) 1(-25.84,-43.237) 1(-25.84,-43.212) 1(-25.84,-43.186) 1(-25.688,-44.787) 1(-25.688,-44.761) 1(-25.688,-44.736) 1(-25.688,-44.71) 1(-25.688,-44.685) 1(-25.688,-44.66) 1(-25.688,-44.634) 1(-25.688,-44.609) 1(-25.688,-44.583) 1(-25.688,-44.558) 1(-25.688,-44.533) 1(-25.688,-44.507) 1(-25.688,-44.482) 1(-25.688,-44.456) 1(-25.688,-44.431) 1(-25.688,-44.406) 1(-25.688,-44.38) 1(-25.688,-44.355) 1(-25.688,-44.329) 1(-25.662,-44.304) 1(-25.662,-44.279) 1(-25.662,-44.253) 1(-25.662,-44.228) 1(-25.662,-44.202) 1(-25.662,-44.177) 1(-25.662,-44.152) 1(-25.662,-44.126) 1(-25.637,-44.101) 1(-25.637,-44.075) 1(-25.637,-44.05) 1(-25.637,-44.025) 1(-25.637,-43.999) 1(-25.611,-43.974) 1(-25.611,-43.948) 1(-25.611,-43.923) 1(-25.586,-43.898) 1(-25.586,-43.872) 1(-25.586,-43.847) 1(-25.561,-43.821) 1(-25.561,-43.796) 1(-25.535,-43.771) 1(-25.535,-43.745) 1(-25.51,-43.72) 1(-25.51,-43.694) 1(-25.484,-43.669) 1(-25.484,-43.644) 1(-25.459,-43.618) 1(-25.434,-45.777) 1(-25.434,-45.752) 1(-25.434,-45.726) 1(-25.434,-45.701) 1(-25.434,-45.676) 1(-25.434,-45.65) 1(-25.434,-45.625) 1(-25.434,-45.599) 1(-25.434,-45.574) 1(-25.434,-45.549) 1(-25.434,-45.523) 1(-25.434,-45.498) 1(-25.434,-45.472) 1(-25.434,-45.447) 1(-25.434,-45.422) 1(-25.434,-45.396) 1(-25.434,-45.371) 1(-25.434,-45.345) 1(-25.434,-45.32) 1(-25.434,-45.295) 1(-25.434,-45.269) 1(-25.434,-45.244) 1(-25.434,-45.218) 1(-25.434,-43.593) 1(-25.434,-43.567) 1(-25.408,-43.542) 1(-25.383,-45.803) 1(-25.383,-45.218) 1(-25.383,-43.517) 1(-25.357,-45.244) 1(-25.357,-43.491) 1(-25.332,-43.466) 1(-25.307,-45.828) 1(-25.307,-45.269) 1(-25.307,-43.44) 1(-25.281,-43.415) 1(-25.256,-45.853) 1(-25.256,-45.295) 1(-25.256,-43.39) 1(-25.23,-43.364) 1(-25.205,-45.32) 1(-25.205,-43.339) 1(-25.18,-45.879) 1(-25.154,-43.313) 1(-25.129,-45.345) 1(-25.129,-43.288) 1(-25.078,-45.904) 1(-25.078,-43.263) 1(-25.053,-45.371) 1(-25.027,-43.237) 1(-24.951,-45.93) 1(-24.951,-45.396) 1(-24.951,-43.212) 1(-24.9,-44.279) 1(-24.9,-44.253) 1(-24.9,-44.228) 1(-24.9,-44.202) 1(-24.9,-44.177) 1(-24.9,-44.152) 1(-24.9,-43.186) 1(-24.875,-44.126) 1(-24.875,-44.101) 1(-24.875,-44.075) 1(-24.875,-44.05) 1(-24.875,-44.025) 1(-24.849,-43.999) 1(-24.849,-43.974) 1(-24.849,-43.948) 1(-24.824,-45.422) 1(-24.824,-43.923) 1(-24.824,-43.898) 1(-24.799,-43.872) 1(-24.799,-43.847) 1(-24.799,-43.161) 1(-24.773,-43.821) 1(-24.748,-45.955) 1(-24.748,-43.796) 1(-24.722,-43.771) 1(-24.697,-43.745) 1(-24.672,-43.72) 1(-24.646,-43.136) 1(-24.621,-43.694) 1(-24.519,-43.669) 1(-24.468,-45.422) 1(-24.341,-45.396) 1(-24.341,-43.669) 1(-24.265,-45.371) 1(-24.265,-43.694) 1(-24.214,-43.72) 1(-24.214,-43.136) 1(-24.189,-45.955) 1(-24.189,-45.345) 1(-24.164,-45.32) 1(-24.164,-43.745) 1(-24.138,-43.771) 1(-24.113,-45.295) 1(-24.113,-43.796) 1(-24.087,-45.269) 1(-24.087,-43.821) 1(-24.062,-45.244) 1(-24.062,-43.847) 1(-24.062,-43.161) 1(-24.037,-45.93) 1(-24.037,-45.218) 1(-24.037,-43.872) 1(-24.011,-45.193) 1(-24.011,-43.923) 1(-24.011,-43.898) 1(-23.986,-45.168) 1(-23.986,-45.142) 1(-23.986,-43.974) 1(-23.986,-43.948) 1(-23.986,-43.186) 1(-23.96,-45.117) 1(-23.96,-45.091) 1(-23.96,-44.025) 1(-23.96,-43.999) 1(-23.935,-45.904) 1(-23.935,-45.066) 1(-23.935,-45.041) 1(-23.935,-44.075) 1(-23.935,-44.05) 1(-23.91,-45.015) 1(-23.91,-44.99) 1(-23.91,-44.964) 1(-23.91,-44.939) 1(-23.91,-44.177) 1(-23.91,-44.152) 1(-23.91,-44.126) 1(-23.91,-44.101) 1(-23.91,-43.212) 1(-23.884,-44.914) 1(-23.884,-44.888) 1(-23.884,-44.863) 1(-23.884,-44.837) 1(-23.884,-44.812) 1(-23.884,-44.279) 1(-23.884,-44.253) 1(-23.884,-44.228) 1(-23.884,-44.202) 1(-23.859,-45.879) 1(-23.833,-43.237) 1(-23.783,-45.853) 1(-23.783,-43.263) 1(-23.732,-45.828) 1(-23.732,-43.288) 1(-23.706,-43.313) 1(-23.681,-45.803) 1(-23.656,-43.339) 1(-23.63,-45.777) 1(-23.63,-43.364) 1(-23.605,-45.752) 1(-23.579,-43.39) 1(-23.554,-45.726) 1(-23.554,-43.415) 1(-23.529,-45.701) 1(-23.529,-43.44) 1(-23.503,-45.676) 1(-23.503,-43.466) 1(-23.478,-43.491) 1(-23.452,-45.65) 1(-23.452,-43.517) 1(-23.427,-45.625) 1(-23.427,-43.542) 1(-23.402,-45.599) 1(-23.402,-43.567) 1(-23.376,-45.574) 1(-23.376,-43.593) 1(-23.351,-45.549) 1(-23.351,-45.523) 1(-23.351,-43.618) 1(-23.325,-45.498) 1(-23.325,-43.669) 1(-23.325,-43.644) 1(-23.3,-45.472) 1(-23.3,-43.694) 1(-23.275,-45.447) 1(-23.275,-45.422) 1(-23.275,-43.745) 1(-23.275,-43.72) 1(-23.249,-45.396) 1(-23.249,-43.796) 1(-23.249,-43.771) 1(-23.224,-45.371) 1(-23.224,-45.345) 1(-23.224,-43.821) 1(-23.198,-45.32) 1(-23.198,-45.295) 1(-23.198,-43.872) 1(-23.198,-43.847) 1(-23.173,-45.269) 1(-23.173,-45.244) 1(-23.173,-43.948) 1(-23.173,-43.923) 1(-23.173,-43.898) 1(-23.148,-45.218) 1(-23.148,-45.193) 1(-23.148,-45.168) 1(-23.148,-44.025) 1(-23.148,-43.999) 1(-23.148,-43.974) 1(-23.122,-45.142) 1(-23.122,-45.117) 1(-23.122,-45.091) 1(-23.122,-44.101) 1(-23.122,-44.075) 1(-23.122,-44.05) 1(-23.097,-45.066) 1(-23.097,-45.041) 1(-23.097,-45.015) 1(-23.097,-44.99) 1(-23.097,-44.202) 1(-23.097,-44.177) 1(-23.097,-44.152) 1(-23.097,-44.126) 1(-23.071,-44.964) 1(-23.071,-44.939) 1(-23.071,-44.914) 1(-23.071,-44.888) 1(-23.071,-44.863) 1(-23.071,-44.837) 1(-23.071,-44.812) 1(-23.071,-44.38) 1(-23.071,-44.355) 1(-23.071,-44.329) 1(-23.071,-44.304) 1(-23.071,-44.279) 1(-23.071,-44.253) 1(-23.071,-44.228) 1(-23.046,-44.787) 1(-23.046,-44.761) 1(-23.046,-44.736) 1(-23.046,-44.71) 1(-23.046,-44.685) 1(-23.046,-44.66) 1(-23.046,-44.634) 1(-23.046,-44.609) 1(-23.046,-44.583) 1(-23.046,-44.558) 1(-23.046,-44.533) 1(-23.046,-44.507) 1(-23.046,-44.482) 1(-23.046,-44.456) 1(-23.046,-44.431) 1(-23.046,-44.406) 1(-22.767,-45.853) 1(-22.767,-45.828) 1(-22.767,-45.803) 1(-22.767,-45.777) 1(-22.767,-45.752) 1(-22.767,-45.726) 1(-22.767,-45.701) 1(-22.767,-45.676) 1(-22.767,-45.65) 1(-22.767,-45.625) 1(-22.767,-45.599) 1(-22.767,-45.574) 1(-22.767,-45.549) 1(-22.767,-45.523) 1(-22.767,-45.498) 1(-22.767,-45.472) 1(-22.767,-45.447) 1(-22.767,-45.422) 1(-22.767,-45.396) 1(-22.767,-45.371) 1(-22.767,-45.345) 1(-22.767,-45.32) 1(-22.767,-45.295) 1(-22.767,-43.771) 1(-22.767,-43.745) 1(-22.767,-43.72) 1(-22.767,-43.694) 1(-22.767,-43.669) 1(-22.767,-43.644) 1(-22.767,-43.618) 1(-22.767,-43.593) 1(-22.767,-43.567) 1(-22.767,-43.542) 1(-22.767,-43.517) 1(-22.767,-43.491) 1(-22.767,-43.466) 1(-22.767,-43.44) 1(-22.767,-43.415) 1(-22.767,-43.39) 1(-22.767,-43.364) 1(-22.767,-43.339) 1(-22.767,-43.313) 1(-22.767,-43.288) 1(-22.767,-43.263) 1(-22.767,-43.237) 1(-22.767,-43.212) 1(-22.767,-43.186) 1(-22.741,-45.879) 1(-22.69,-45.904) 1(-22.69,-45.295) 1(-22.64,-45.32) 1(-22.589,-45.93) 1(-22.563,-45.345) 1(-22.462,-45.955) 1(-22.386,-45.345) 1(-22.309,-45.32) 1(-22.259,-45.295) 1(-22.233,-45.269) 1(-22.208,-45.244) 1(-22.208,-45.218) 1(-22.182,-45.193) 1(-22.182,-45.168) 1(-22.157,-45.142) 1(-22.157,-45.117) 1(-22.157,-45.091) 1(-22.157,-45.066) 1(-22.132,-45.041) 1(-22.132,-45.015) 1(-22.132,-44.99) 1(-22.132,-44.964) 1(-22.132,-44.939) 1(-22.132,-44.914) 1(-22.132,-44.888) 1(-22.132,-44.863) 1(-22.132,-44.837) 1(-22.132,-44.812) 1(-22.132,-44.787) 1(-22.132,-44.761) 1(-22.132,-44.736) 1(-22.132,-44.71) 1(-22.132,-44.685) 1(-22.132,-44.66) 1(-22.132,-44.634) 1(-22.132,-44.609) 1(-22.132,-44.583) 1(-22.132,-44.558) 1(-22.132,-44.533) 1(-22.132,-44.507) 1(-22.132,-44.482) 1(-22.132,-44.456) 1(-22.132,-44.431) 1(-22.132,-44.406) 1(-22.132,-44.38) 1(-22.132,-44.355) 1(-22.132,-44.329) 1(-22.132,-44.304) 1(-22.132,-44.279) 1(-22.132,-44.253) 1(-22.132,-44.228) 1(-22.132,-44.202) 1(-22.132,-44.177) 1(-22.132,-44.152) 1(-22.132,-44.126) 1(-22.132,-44.101) 1(-22.132,-44.075) 1(-22.132,-44.05) 1(-22.132,-44.025) 1(-22.132,-43.999) 1(-22.132,-43.974) 1(-22.132,-43.948) 1(-22.132,-43.923) 1(-22.132,-43.898) 1(-22.132,-43.872) 1(-22.132,-43.847) 1(-22.132,-43.821) 1(-22.132,-43.796) 1(-22.132,-43.161) 1(-22.132,-43.136) 1(-22.132,-43.11) 1(-22.132,-43.085) 1(-22.132,-43.059) 1(-22.132,-43.034) 1(-22.132,-43.009) 1(-22.132,-42.983) 1(-22.132,-42.958) 1(-22.132,-42.932) 1(-22.132,-42.907) 1(-22.132,-42.882) 1(-22.132,-42.856) 1(-22.132,-42.831) 1(-22.132,-42.805) 1(-22.132,-42.78) 1(-22.132,-42.755) 1(-22.132,-42.729) 1(-22.132,-42.704) 1(-22.132,-42.678) 1(-22.132,-42.653) 1(-22.132,-42.628) 1(-22.132,-42.602) 1(-22.132,-42.577) 1(-22.132,-42.551) 1(-22.132,-42.526) 1(-22.132,-42.501) 1(-22.132,-42.475) 1(-22.132,-42.45) 1(-22.132,-42.424) 1(-22.132,-42.399) 1(-22.132,-42.374) 1(-22.132,-42.348) 1(-22.055,-42.348) 1(-21.979,-45.955) 1(-21.979,-42.374) 1(-21.878,-42.399) 1(-21.852,-45.93) 1(-21.801,-42.424) 1(-21.776,-45.904) 1(-21.725,-45.879) 1(-21.7,-42.45) 1(-21.674,-45.853) 1(-21.624,-45.828) 1(-21.624,-42.475) 1(-21.598,-45.803) 1(-21.547,-45.777) 1(-21.522,-45.752) 1(-21.522,-42.501) 1(-21.497,-45.726) 1(-21.497,-45.701) 1(-21.471,-45.676) 1(-21.446,-45.65) 1(-21.446,-42.526) 1(-21.42,-45.625) 1(-21.42,-45.599) 1(-21.395,-45.574) 1(-21.395,-45.549) 1(-21.37,-45.523) 1(-21.37,-45.498) 1(-21.37,-45.472) 1(-21.344,-45.447) 1(-21.344,-45.422) 1(-21.344,-45.396) 1(-21.344,-45.371) 1(-21.344,-42.551) 1(-21.319,-45.345) 1(-21.319,-45.32) 1(-21.319,-45.295) 1(-21.319,-45.269) 1(-21.319,-45.244) 1(-21.319,-45.218) 1(-21.319,-45.193) 1(-21.293,-45.168) 1(-21.293,-45.142) 1(-21.293,-45.117) 1(-21.293,-45.091) 1(-21.293,-45.066) 1(-21.293,-45.041) 1(-21.293,-45.015) 1(-21.293,-44.99) 1(-21.293,-44.964) 1(-21.293,-44.939) 1(-21.293,-44.914) 1(-21.293,-44.888) 1(-21.293,-44.863) 1(-21.293,-44.837) 1(-21.293,-44.812) 1(-21.293,-44.787) 1(-21.293,-44.761) 1(-21.293,-44.736) 1(-21.293,-44.71) 1(-21.293,-44.685) 1(-21.293,-44.66) 1(-21.293,-44.634) 1(-21.293,-44.609) 1(-21.293,-44.583) 1(-21.293,-44.558) 1(-21.293,-44.533) 1(-21.293,-44.507) 1(-21.293,-44.482) 1(-21.293,-44.456) 1(-21.293,-44.431) 1(-21.293,-44.406) 1(-21.293,-44.38) 1(-21.293,-44.355) 1(-21.293,-44.329) 1(-21.293,-44.304) 1(-21.293,-44.279) 1(-21.293,-44.253) 1(-21.293,-44.228) 1(-21.293,-44.202) 1(-21.293,-44.177) 1(-21.293,-44.152) 1(-21.293,-44.126) 1(-21.293,-44.101) 1(-21.293,-44.075) 1(-21.293,-44.05) 1(-21.293,-44.025) 1(-21.293,-43.999) 1(-21.293,-43.974) 1(-21.293,-43.948) 1(-21.293,-43.923) 1(-21.293,-43.898) 1(-21.293,-43.872) 1(-21.293,-43.847) 1(-21.293,-43.821) 1(-21.293,-43.796) 1(-21.293,-43.161) 1(-21.293,-43.136) 1(-21.293,-43.11) 1(-21.293,-43.085) 1(-21.293,-43.059) 1(-21.293,-43.034) 1(-21.293,-43.009) 1(-21.293,-42.983) 1(-21.293,-42.958) 1(-21.293,-42.932) 1(-21.293,-42.907) 1(-21.293,-42.882) 1(-21.293,-42.856) 1(-21.293,-42.831) 1(-21.293,-42.805) 1(-21.293,-42.78) 1(-21.293,-42.755) 1(-21.293,-42.729) 1(-21.293,-42.704) 1(-21.293,-42.678) 1(-21.293,-42.653) 1(-21.293,-42.628) 1(-21.293,-42.602) 1(-21.293,-42.577) 1(-20.862,-43.771) 1(-20.862,-43.745) 1(-20.862,-43.72) 1(-20.862,-43.694) 1(-20.862,-43.669) 1(-20.862,-43.644) 1(-20.862,-43.618) 1(-20.862,-43.593) 1(-20.862,-43.567) 1(-20.862,-43.542) 1(-20.862,-43.517) 1(-20.862,-43.491) 1(-20.862,-43.466) 1(-20.862,-43.44) 1(-20.862,-43.415) 1(-20.862,-43.39) 1(-20.862,-43.364) 1(-20.862,-43.339) 1(-20.862,-43.313) 1(-20.862,-43.288) 1(-20.862,-43.263) 1(-20.862,-43.237) 1(-20.862,-43.212) 1(-20.862,-43.186) 1(-20.455,-45.904) 1(-20.455,-45.879) 1(-20.455,-45.853) 1(-20.455,-45.828) 1(-20.455,-45.803) 1(-20.455,-45.777) 1(-20.455,-45.752) 1(-20.455,-45.726) 1(-20.455,-45.701) 1(-20.455,-45.676) 1(-20.455,-45.65) 1(-20.455,-45.625) 1(-20.455,-45.599) 1(-20.455,-45.574) 1(-20.455,-45.549) 1(-20.455,-45.523) 1(-20.455,-45.498) 1(-20.455,-45.472) 1(-20.455,-45.447) 1(-20.455,-45.422) 1(-20.455,-45.396) 1(-20.455,-45.371) 1(-20.455,-45.345) 1(-20.455,-45.32) 1(-20.455,-45.295) 1(-20.455,-45.269) 1(-20.455,-45.244) 1(-20.455,-45.218) 1(-20.455,-45.193) 1(-20.455,-45.168) 1(-20.455,-45.142) 1(-20.455,-45.117) 1(-20.455,-45.091) 1(-20.455,-45.066) 1(-20.455,-45.041) 1(-20.455,-45.015) 1(-20.455,-44.99) 1(-20.455,-44.964) 1(-20.455,-44.939) 1(-20.455,-44.914) 1(-20.455,-44.888) 1(-20.455,-44.863) 1(-20.455,-44.837) 1(-20.455,-44.812) 1(-20.455,-44.787) 1(-20.455,-44.761) 1(-20.455,-44.736) 1(-20.455,-44.71) 1(-20.455,-44.685) 1(-20.455,-44.66) 1(-20.455,-44.634) 1(-20.455,-44.609) 1(-20.455,-44.583) 1(-20.455,-44.558) 1(-20.455,-44.533) 1(-20.455,-44.507) 1(-20.455,-44.482) 1(-20.455,-44.456) 1(-20.455,-44.431) 1(-20.455,-44.406) 1(-20.455,-44.38) 1(-20.455,-44.355) 1(-20.455,-44.329) 1(-20.455,-44.304) 1(-20.455,-44.279) 1(-20.455,-44.253) 1(-20.455,-44.228) 1(-20.455,-44.202) 1(-20.455,-44.177) 1(-20.455,-44.152) 1(-20.455,-44.126) 1(-20.455,-44.101) 1(-20.455,-44.075) 1(-20.43,-44.05) 1(-20.43,-44.025) 1(-20.43,-43.999) 1(-20.43,-43.974) 1(-20.43,-43.948) 1(-20.43,-43.923) 1(-20.404,-43.898) 1(-20.404,-43.872) 1(-20.404,-43.847) 1(-20.404,-43.821) 1(-20.379,-43.796) 1(-20.379,-43.771) 1(-20.379,-43.745) 1(-20.354,-43.72) 1(-20.354,-43.694) 1(-20.354,-43.669) 1(-20.328,-43.644) 1(-20.328,-43.618) 1(-20.303,-43.593) 1(-20.277,-43.567) 1(-20.277,-43.542) 1(-20.252,-43.517) 1(-20.227,-43.491) 1(-20.227,-43.466) 1(-20.201,-43.44) 1(-20.176,-43.415) 1(-20.15,-43.39) 1(-20.125,-43.364) 1(-20.074,-43.339) 1(-20.049,-43.313) 1(-19.998,-43.288) 1(-19.973,-43.263) 1(-19.922,-43.237) 1(-19.846,-43.212) 1(-19.769,-43.186) 1(-19.668,-44.863) 1(-19.668,-44.837) 1(-19.668,-44.812) 1(-19.668,-44.787) 1(-19.668,-44.761) 1(-19.668,-44.736) 1(-19.668,-44.71) 1(-19.668,-44.685) 1(-19.668,-44.66) 1(-19.668,-44.634) 1(-19.668,-44.126) 1(-19.668,-44.101) 1(-19.668,-44.075) 1(-19.668,-43.161) 1(-19.642,-45.904) 1(-19.642,-45.879) 1(-19.642,-45.853) 1(-19.642,-45.828) 1(-19.642,-45.803) 1(-19.642,-45.777) 1(-19.642,-45.752) 1(-19.642,-45.726) 1(-19.642,-45.701) 1(-19.642,-45.676) 1(-19.642,-45.65) 1(-19.642,-45.625) 1(-19.642,-45.599) 1(-19.642,-45.015) 1(-19.642,-44.99) 1(-19.642,-44.964) 1(-19.642,-44.939) 1(-19.642,-44.914) 1(-19.642,-44.888) 1(-19.642,-44.05) 1(-19.642,-44.025) 1(-19.642,-43.999) 1(-19.642,-43.974) 1(-19.642,-43.948) 1(-19.617,-45.599) 1(-19.617,-45.066) 1(-19.617,-45.041) 1(-19.617,-43.923) 1(-19.617,-43.898) 1(-19.592,-45.65) 1(-19.592,-45.625) 1(-19.592,-45.142) 1(-19.592,-45.117) 1(-19.592,-45.091) 1(-19.592,-43.872) 1(-19.592,-43.847) 1(-19.566,-45.676) 1(-19.566,-45.168) 1(-19.566,-44.152) 1(-19.566,-43.821) 1(-19.541,-45.701) 1(-19.541,-45.218) 1(-19.541,-45.193) 1(-19.541,-43.796) 1(-19.515,-45.726) 1(-19.515,-45.244) 1(-19.515,-43.771) 1(-19.515,-43.136) 1(-19.49,-45.752) 1(-19.49,-45.269) 1(-19.49,-43.745) 1(-19.465,-45.295) 1(-19.465,-44.634) 1(-19.465,-43.72) 1(-19.439,-45.777) 1(-19.439,-45.32) 1(-19.414,-45.803) 1(-19.388,-45.828) 1(-19.388,-45.345) 1(-19.388,-43.694) 1(-19.363,-45.371) 1(-19.363,-44.177) 1(-19.338,-45.853) 1(-19.312,-45.396) 1(-19.312,-43.669) 1(-19.287,-45.879) 1(-19.287,-44.66) 1(-19.236,-45.904) 1(-19.211,-45.422) 1(-19.185,-44.202) 1(-19.16,-45.93) 1(-19.109,-44.685) 1(-19.033,-45.955) 1(-19.033,-43.136) 1(-19.007,-45.422) 1(-19.007,-44.71) 1(-19.007,-44.228) 1(-19.007,-43.669) 1(-18.957,-44.736) 1(-18.931,-45.396) 1(-18.906,-44.761) 1(-18.88,-45.371) 1(-18.855,-45.345) 1(-18.855,-44.787) 1(-18.855,-43.694) 1(-18.855,-43.161) 1(-18.83,-45.32) 1(-18.83,-44.812) 1(-18.83,-44.253) 1(-18.804,-45.295) 1(-18.804,-44.863) 1(-18.804,-44.837) 1(-18.779,-45.269) 1(-18.779,-45.244) 1(-18.779,-44.914) 1(-18.779,-44.888) 1(-18.753,-45.218) 1(-18.753,-45.193) 1(-18.753,-45.168) 1(-18.753,-45.142) 1(-18.753,-45.015) 1(-18.753,-44.99) 1(-18.753,-44.964) 1(-18.753,-44.939) 1(-18.753,-43.72) 1(-18.728,-45.117) 1(-18.728,-45.091) 1(-18.728,-45.066) 1(-18.728,-45.041) 1(-18.728,-43.186) 1(-18.703,-44.279) 1(-18.677,-43.745) 1(-18.652,-45.955) 1(-18.626,-43.212) 1(-18.601,-44.304) 1(-18.601,-43.771) 1(-18.55,-43.796) 1(-18.525,-45.93) 1(-18.525,-44.329) 1(-18.525,-43.237) 1(-18.499,-43.821) 1(-18.474,-44.355) 1(-18.449,-45.904) 1(-18.449,-43.847) 1(-18.449,-43.263) 1(-18.423,-44.38) 1(-18.398,-43.872) 1(-18.372,-45.879) 1(-18.372,-44.406) 1(-18.372,-43.898) 1(-18.372,-43.288) 1(-18.347,-45.853) 1(-18.322,-44.431) 1(-18.322,-43.923) 1(-18.296,-45.828) 1(-18.296,-44.456) 1(-18.296,-43.948) 1(-18.296,-43.313) 1(-18.271,-45.803) 1(-18.245,-44.482) 1(-18.245,-43.339) 1(-18.22,-45.777) 1(-18.22,-44.507) 1(-18.22,-43.948) 1(-18.22,-43.923) 1(-18.22,-43.898) 1(-18.22,-43.872) 1(-18.22,-43.847) 1(-18.22,-43.821) 1(-18.22,-43.796) 1(-18.22,-43.771) 1(-18.22,-43.745) 1(-18.22,-43.72) 1(-18.22,-43.694) 1(-18.22,-43.669) 1(-18.22,-43.644) 1(-18.22,-43.618) 1(-18.22,-43.593) 1(-18.22,-43.567) 1(-18.22,-43.542) 1(-18.22,-43.517) 1(-18.22,-43.491) 1(-18.22,-43.466) 1(-18.22,-43.44) 1(-18.22,-43.415) 1(-18.22,-43.39) 1(-18.22,-43.364) 1(-18.195,-45.752) 1(-18.195,-44.533) 1(-18.169,-45.726) 1(-18.169,-44.558) 1(-18.144,-45.701) 1(-18.144,-44.583) 1(-18.118,-45.676) 1(-18.118,-45.65) 1(-18.118,-44.634) 1(-18.118,-44.609) 1(-18.093,-45.625) 1(-18.093,-44.66) 1(-18.068,-45.599) 1(-18.068,-45.574) 1(-18.068,-44.71) 1(-18.068,-44.685) 1(-18.042,-45.549) 1(-18.042,-45.523) 1(-18.042,-44.761) 1(-18.042,-44.736) 1(-18.017,-45.498) 1(-18.017,-45.472) 1(-18.017,-44.837) 1(-18.017,-44.812) 1(-18.017,-44.787) 1(-17.991,-45.447) 1(-17.991,-45.422) 1(-17.991,-45.396) 1(-17.991,-45.371) 1(-17.991,-44.914) 1(-17.991,-44.888) 1(-17.991,-44.863) 1(-17.966,-45.345) 1(-17.966,-45.32) 1(-17.966,-45.295) 1(-17.966,-45.269) 1(-17.966,-45.244) 1(-17.966,-45.218) 1(-17.966,-45.193) 1(-17.966,-45.168) 1(-17.966,-45.142) 1(-17.966,-45.117) 1(-17.966,-45.091) 1(-17.966,-45.066) 1(-17.966,-45.041) 1(-17.966,-45.015) 1(-17.966,-44.99) 1(-17.966,-44.964) 1(-17.966,-44.939) 1(-17.509,-45.65) 1(-17.509,-45.625) 1(-17.509,-45.599) 1(-17.509,-45.574) 1(-17.509,-45.549) 1(-17.509,-45.523) 1(-17.509,-45.498) 1(-17.509,-45.472) 1(-17.509,-45.447) 1(-17.509,-45.422) 1(-17.509,-45.396) 1(-17.509,-45.371) 1(-17.509,-45.345) 1(-17.509,-45.32) 1(-17.509,-45.295) 1(-17.509,-45.269) 1(-17.509,-45.244) 1(-17.509,-45.218) 1(-17.509,-45.193) 1(-17.509,-45.168) 1(-17.509,-45.142) 1(-17.509,-45.117) 1(-17.509,-45.091) 1(-17.509,-45.066) 1(-17.509,-45.041) 1(-17.509,-45.015) 1(-17.509,-44.99) 1(-17.509,-44.964) 1(-17.509,-44.939) 1(-17.509,-44.914) 1(-17.509,-44.888) 1(-17.509,-44.863) 1(-17.509,-44.837) 1(-17.509,-44.812) 1(-17.509,-44.787) 1(-17.509,-44.761) 1(-17.509,-44.736) 1(-17.509,-44.71) 1(-17.509,-44.685) 1(-17.509,-44.66) 1(-17.509,-44.634) 1(-17.509,-44.609) 1(-17.509,-44.583) 1(-17.509,-44.558) 1(-17.509,-44.533) 1(-17.509,-44.507) 1(-17.509,-44.482) 1(-17.509,-44.456) 1(-17.509,-44.431) 1(-17.509,-44.406) 1(-17.509,-44.38) 1(-17.509,-44.355) 1(-17.509,-44.329) 1(-17.509,-44.304) 1(-17.509,-44.279) 1(-17.509,-44.253) 1(-17.509,-44.228) 1(-17.509,-44.202) 1(-17.509,-44.177) 1(-17.509,-44.152) 1(-17.509,-44.126) 1(-17.509,-44.101) 1(-17.509,-44.075) 1(-17.509,-44.05) 1(-17.509,-44.025) 1(-17.509,-43.999) 1(-17.509,-43.974) 1(-17.509,-43.948) 1(-17.509,-43.923) 1(-17.509,-43.898) 1(-17.509,-43.872) 1(-17.509,-43.847) 1(-17.509,-43.821) 1(-17.509,-43.796) 1(-17.509,-43.771) 1(-17.458,-45.676) 1(-17.407,-45.701) 1(-17.356,-45.726) 1(-17.356,-42.958) 1(-17.356,-42.932) 1(-17.356,-42.907) 1(-17.356,-42.882) 1(-17.356,-42.856) 1(-17.356,-42.831) 1(-17.356,-42.805) 1(-17.356,-42.78) 1(-17.356,-42.755) 1(-17.356,-42.729) 1(-17.356,-42.704) 1(-17.356,-42.678) 1(-17.356,-42.653) 1(-17.356,-42.628) 1(-17.356,-42.602) 1(-17.356,-42.577) 1(-17.356,-42.551) 1(-17.356,-42.526) 1(-17.356,-42.501) 1(-17.356,-42.475) 1(-17.356,-42.45) 1(-17.356,-42.424) 1(-17.356,-42.399) 1(-17.356,-42.374) 1(-17.356,-42.348) 1(-17.356,-42.323) 1(-17.356,-42.297) 1(-17.356,-42.272) 1(-17.356,-42.247) 1(-17.356,-42.221) 1(-17.331,-42.196) 1(-17.306,-45.752) 1(-17.28,-42.958) 1(-17.255,-45.777) 1(-17.255,-42.17) 1(-17.229,-42.932) 1(-17.179,-45.803) 1(-17.179,-42.907) 1(-17.179,-42.145) 1(-17.128,-42.882) 1(-17.102,-45.828) 1(-17.077,-42.856) 1(-17.077,-42.12) 1(-17.026,-45.853) 1(-17.001,-42.831) 1(-16.95,-42.094) 1(-16.925,-45.879) 1(-16.899,-42.805) 1(-16.823,-45.904) 1(-16.823,-42.78) 1(-16.823,-42.069) 1(-16.696,-42.755) 1(-16.671,-45.93) 1(-16.645,-45.168) 1(-16.645,-45.142) 1(-16.645,-45.117) 1(-16.645,-45.091) 1(-16.645,-45.066) 1(-16.645,-45.041) 1(-16.645,-45.015) 1(-16.645,-44.99) 1(-16.645,-44.964) 1(-16.645,-44.939) 1(-16.645,-44.914) 1(-16.645,-44.888) 1(-16.645,-44.863) 1(-16.645,-44.837) 1(-16.645,-44.812)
